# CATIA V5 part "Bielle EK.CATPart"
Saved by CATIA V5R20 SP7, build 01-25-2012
Part number: Bielle EK
Publications: "Point.1", "Droite.2", "Droite.3"
Bounding box of the stored display mesh (mm): x -10 to 10, y 0 to 0, z 0 to 450
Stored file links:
  U:\IAO\IAO\IAO\Bielle EK.CATPart
  U:\IAO\IAO\IAO\Squelette.CATProduct
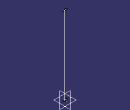
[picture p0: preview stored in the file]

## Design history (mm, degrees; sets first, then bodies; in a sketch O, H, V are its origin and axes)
External parameters (linked from other documents)
  `External.Longueur X4` = 450 mm
  `External.Longueur Demi Pivot` = 10 mm
Body1 (main body)
  Point1: (0, 0, 0)
  Line1: type PtDir, RefPoint Point1, Direction xy-plane, Start 0, End 450 {= `External.Longueur X4`}
  Line2: type PtDir, RefPoint Point1, Direction yz-plane, Start -10, End 10 {= `External.Longueur Demi Pivot`}
  Line3: type PtDir, RefPoint vertex of Line1, Direction yz-plane, Start -10, End 10 {= `External.Longueur Demi Pivot`}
